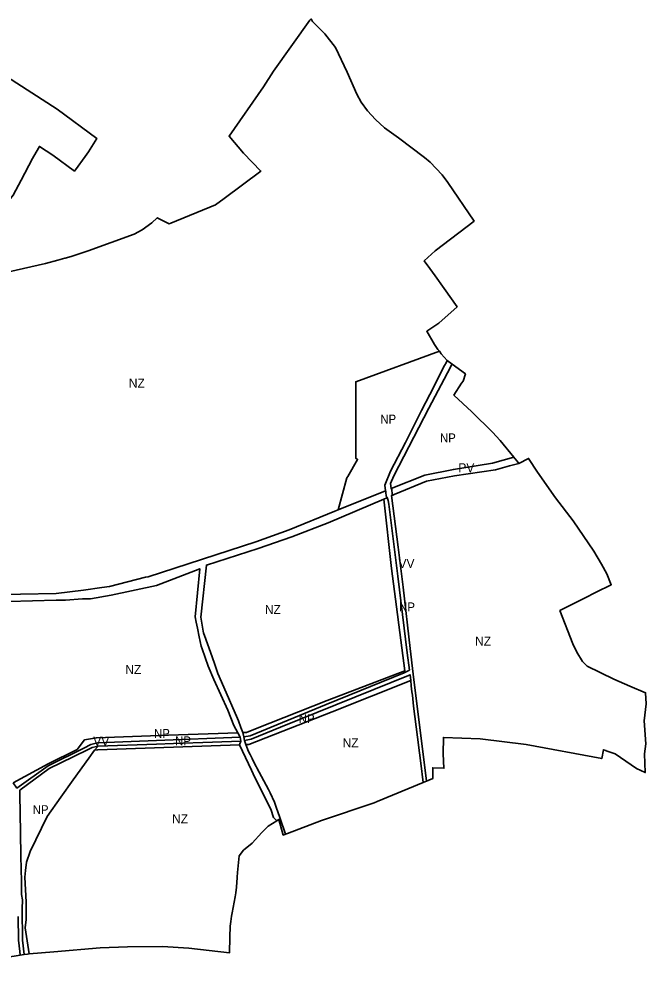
# Model space of a CAD drawing. Extents: x -650451 to -642268, y -1075216 to -1066610.
# Drawn here: x -643317 to -642268, y -1070593 to -1069004 of the extents above; entities that cross this region are included whole.
import ezdxf

# ---------------------------------------------------------------- set-up
doc = ezdxf.new("R2010")
doc.units = 0
doc.header["$LTSCALE"] = 6
doc.layers.add('1', color=7, linetype='Continuous', lineweight=35)
doc.layers.add('2', color=7, linetype='Continuous')
doc.layers.add('3', color=7, linetype='Continuous')

msp = doc.modelspace()

# ---------------------------------------------------------------- linework, layer by layer
at = {"layer": '1'}
for p, q in [((-642600.39, -1069574.87), (-642592.12, -1069580.95)), ((-642782.69, -1069824.93), (-642703.57, -1069792.88)), ((-642701.17, -1069804.49), (-642706.3, -1069806.69)), ((-642950.42, -1070197.58), (-642946.24, -1070204.83)), ((-642942.12, -1070197.4), (-642940.12, -1070204.42)), ((-642947.42, -1070217.64), (-642945.59, -1070211.49)), ((-642946.24, -1070204.83), (-642945.59, -1070211.49)), ((-642939.51, -1070210.35), (-642940.12, -1070204.42)), ((-642939.51, -1070210.35), (-642936.88, -1070217.27)), ((-643184.22, -1070220.08), (-643190.42, -1070226.99)), ((-642634.72, -1070278.46), (-642640.39, -1070280.82)), ((-643314.51, -1070569.69), (-643307.99, -1070568.66))]:
    msp.add_line(p, q, dxfattribs=at)
for points in [[(-642613.34, -1069559.68), (-642615.67, -1069556.39), (-642621.38, -1069548.32), (-642634.53, -1069526.26), (-642614.21, -1069512.57), (-642583.52, -1069485.34), (-642605.44, -1069454.72), (-642620.56, -1069433.59), (-642629.27, -1069421.41), (-642638.46, -1069408.57), (-642620.16, -1069391.43), (-642555.29, -1069342.03), (-642599.01, -1069277.25), (-642608.74, -1069264.5), (-642628.74, -1069243.14), (-642638.04, -1069235.61), (-642681.9, -1069202.83), (-642705.02, -1069185.92), (-642720.3, -1069172.09), (-642733.38, -1069157.41), (-642744.33, -1069142.96), (-642751.46, -1069129.7), (-642767.68, -1069092.94), (-642787.11, -1069051.51), (-642804.62, -1069028.48), (-642825.24, -1069008.13), (-642827.83, -1069003.93), (-642829.78, -1069005.85), (-642890.6, -1069090.98), (-642907.25, -1069117.59), (-642964.96, -1069199.73), (-642940.94, -1069228.19), (-642911.84, -1069258.15), (-642973.15, -1069303.98), (-642987.79, -1069314.92), (-643062.55, -1069345.13), (-643065.5, -1069346.32), (-643079.76, -1069339.05), (-643085.3, -1069336.22), (-643094.39, -1069344.93), (-643110.6, -1069356.48), (-643123.85, -1069363.76), (-643200.76, -1069391.51), (-643229.39, -1069400.85), (-643239.08, -1069403.7), (-643239.98, -1069403.97), (-643251.76, -1069407.44), (-643272.03, -1069412.65), (-643333.4, -1069426.8)], [(-643345.65, -1069418.15), (-643392.16, -1069386.88), (-643356.97, -1069342), (-643349.53, -1069332.52), (-643334.48, -1069309.27), (-643326.25, -1069298.47), (-643312.8, -1069273.59), (-643294.09, -1069237.23), (-643291.96, -1069233.54), (-643282.39, -1069216.93), (-643259.72, -1069231.55), (-643223.83, -1069258.21), (-643222.16, -1069255.97), (-643205.79, -1069233.92), (-643199.98, -1069226.2), (-643186.13, -1069203.94), (-643252.85, -1069154.56), (-643337.18, -1069100.04), (-643350.47, -1069098.91), (-643355.79, -1069099.42), (-643386.77, -1069143.32)], [(-642613.34, -1069559.68), (-642753.18, -1069610.65), (-642753.25, -1069738.59), (-642750.08, -1069740.57), (-642766.27, -1069769), (-642767.89, -1069771.42), (-642782.69, -1069824.93)], [(-642600.39, -1069574.87), (-642610.43, -1069563.79), (-642613.34, -1069559.68)], [(-642703.57, -1069792.88), (-642704.33, -1069783.54), (-642694.96, -1069760.17), (-642670.2, -1069712.37), (-642643.19, -1069658.58), (-642629.16, -1069631.94), (-642604.54, -1069583.67), (-642602.09, -1069578.86), (-642600.39, -1069574.87)], [(-642592.12, -1069580.95), (-642593.91, -1069584.46), (-642594.761, -1069586.091), (-642630.64, -1069654.82), (-642689.63, -1069767.81), (-642694.92, -1069780.68), (-642693.99, -1069788.85)], [(-642592.12, -1069580.95), (-642569.7, -1069597.42), (-642573.53, -1069609.34), (-642576.02, -1069613.14), (-642588.93, -1069632.86), (-642559.13, -1069661.18), (-642524.24, -1069694.66), (-642511.74, -1069708.63), (-642488.97, -1069736.54), (-642488.71, -1069736.85)], [(-642488.71, -1069736.85), (-642524.14, -1069746.8), (-642589.86, -1069757.1), (-642637.44, -1069766.81), (-642693.99, -1069788.85)], [(-642480.33, -1069747.1), (-642464, -1069738.83), (-642448.9, -1069761.88), (-642419.08, -1069804.61), (-642389.46, -1069843.4), (-642354.94, -1069894.06), (-642342.3, -1069915.7), (-642332.99, -1069931.63), (-642325.76, -1069950.18), (-642350.88, -1069962.69), (-642370.76, -1069972.6), (-642411.52, -1069993.17), (-642390.2, -1070048.75), (-642383.53, -1070062.65), (-642374.12, -1070078.53), (-642366.26, -1070086.08), (-642321.52, -1070108.08), (-642294.55, -1070119.7), (-642268.3, -1070130.58), (-642267.61, -1070149.35), (-642270.93, -1070177.77), (-642267.95, -1070216.15), (-642270.15, -1070232.65), (-642268.98, -1070264.17), (-642283.43, -1070257.44), (-642319.35, -1070232.74), (-642334.07, -1070227.7), (-642335.01, -1070227.38), (-642338.84, -1070226.07), (-642341.74, -1070240.74), (-642468.21, -1070217.46), (-642544.88, -1070207.97), (-642606.43, -1070205.41), (-642607.11, -1070232.78), (-642605.67, -1070256.87), (-642624.37, -1070256.25), (-642624.34, -1070274.14), (-642630.76, -1070276.81), (-642630.85, -1070276.85), (-642634.72, -1070278.46)], [(-642480.33, -1069747.1), (-642483.3, -1069743.48), (-642486.84, -1069739.15), (-642487.57, -1069738.25), (-642488.71, -1069736.85)], [(-642480.33, -1069747.1), (-642495.77, -1069751.44), (-642519.23, -1069757.95), (-642587.7, -1069767.66), (-642634.56, -1069777.05), (-642688.78, -1069798.98), (-642691.36, -1069800.03)], [(-642940.12, -1070204.42), (-642930.02, -1070202.54), (-642802.38, -1070150.51), (-642671.9, -1070097.32), (-642663.28, -1070092.67), (-642667.19, -1070063.71), (-642682.78, -1069935.98), (-642697.64, -1069815.14), (-642698.77, -1069809.17), (-642700.34, -1069804.12), (-642701.17, -1069804.49)], [(-642703.57, -1069792.88), (-642702.88, -1069794.95), (-642702.69, -1069795.44), (-642702.12, -1069801.89), (-642701.95, -1069802.35), (-642701.17, -1069804.49)], [(-642691.36, -1069800.03), (-642691.98, -1069798.57), (-642692.18, -1069798.08), (-642692.81, -1069791.58), (-642693, -1069791.05), (-642693.99, -1069788.85)], [(-642691.36, -1069800.03), (-642693.36, -1069800.94), (-642682.32, -1069887.43), (-642674.06, -1069953.91), (-642662.41, -1070056.78), (-642657.01, -1070099.49), (-642653.52, -1070126.99), (-642640.31, -1070233.47), (-642634.72, -1070278.46)], [(-642942.12, -1070197.4), (-642945.15, -1070188.91), (-642949.08, -1070177.91), (-642950.79, -1070174.04), (-642974.01, -1070121.34), (-642983.92, -1070098.38), (-642989.73, -1070081.96), (-642996.28, -1070063.04), (-643003.33, -1070042.66), (-643003.95, -1070040.85), (-643007.79, -1070030.29), (-643008.67, -1070027.69), (-643012.58, -1070004.56), (-643002.88, -1069917.33), (-642916.68, -1069889.38), (-642860.07, -1069870.09), (-642799.26, -1069846.42), (-642706.3, -1069806.69)], [(-642942.12, -1070197.4), (-642936.02, -1070197.23), (-642921.03, -1070191.32), (-642801.19, -1070143.75), (-642671.23, -1070094.16), (-642693.2, -1069922.89), (-642706.3, -1069806.69)], [(-643419.62, -1069963.66), (-643419.27, -1069968.58), (-643373.94, -1069966.68), (-643254.27, -1069964.45), (-643208.32, -1069959.24), (-643177.66, -1069954.76), (-643165.1, -1069952.97), (-643104.67, -1069937.61), (-643100.67, -1069936.63), (-642920.18, -1069878.46), (-642864.62, -1069858.27), (-642788.08, -1069827.14), (-642782.69, -1069824.93)], [(-642950.42, -1070197.58), (-642957.12, -1070185.74), (-642967.1, -1070159.77), (-642990.44, -1070108.4), (-643000.04, -1070086.48), (-643010.27, -1070057.2), (-643011.64, -1070052.91), (-643015.19, -1070037.32), (-643017.99, -1070022.61), (-643019.9, -1070012.55), (-643021.83, -1070003.51), (-643014.02, -1069923.38), (-643086.47, -1069951.48), (-643162.5, -1069967.46), (-643196.69, -1069973.45), (-643205.72, -1069973.77), (-643210.04, -1069973.92), (-643238.86, -1069975.91), (-643254.4, -1069976.15), (-643373.64, -1069979.08)], [(-642661.13, -1070110.48), (-642662.32, -1070100.64), (-642879.2, -1070188.43), (-642928.07, -1070208.21), (-642939.51, -1070210.35)], [(-642661.13, -1070110.48), (-642792.87, -1070162.36), (-642931.88, -1070217.1), (-642936.88, -1070217.27)], [(-642640.39, -1070280.82), (-642644.06, -1070248.54), (-642646.76, -1070231.29), (-642649.61, -1070205.1), (-642656.54, -1070153.14), (-642658.44, -1070135.02), (-642659.28, -1070129.09), (-642660.65, -1070119.2), (-642661.13, -1070110.48)], [(-643326.26, -1070281.43), (-643267.55, -1070249.49), (-643219.4, -1070225.8), (-643207.1, -1070209.72), (-643187.06, -1070205.98), (-643066.26, -1070201.69), (-642950.42, -1070197.58)], [(-643326.26, -1070281.43), (-643320, -1070290.2), (-643267.75, -1070252.77), (-643208.09, -1070223.14), (-643196.16, -1070217.22), (-643185.16, -1070214.62), (-643086.36, -1070210.57), (-642946.24, -1070204.83)], [(-642945.59, -1070211.49), (-642992.64, -1070213.18), (-643058.07, -1070215.38), (-643086.58, -1070216.57), (-643184.22, -1070220.08)], [(-642936.88, -1070217.27), (-642932.4, -1070228.91), (-642929.96, -1070233.8), (-642926.46, -1070240.85), (-642922.84, -1070248.13), (-642919.99, -1070253.87), (-642918.56, -1070256.37), (-642899.12, -1070292.53), (-642896.56, -1070297.95), (-642889.22, -1070313.53), (-642886.52, -1070321.86), (-642880.4, -1070339.24), (-642870.91, -1070367.41)], [(-643184.22, -1070220.08), (-643194.11, -1070222.44), (-643199.63, -1070225.11), (-643225.87, -1070237.84), (-643265.93, -1070257.27), (-643315.11, -1070293.76), (-643315.02, -1070300.7), (-643314.14, -1070364.39), (-643313.65, -1070403.8), (-643312.07, -1070446.44), (-643312.07, -1070468.03), (-643310.68, -1070477.03), (-643311.45, -1070491.88), (-643310.74, -1070544.5), (-643307.99, -1070568.66)], [(-643190.42, -1070226.99), (-643199.67, -1070240.13), (-643225.66, -1070276.41), (-643246.36, -1070305.06), (-643269.16, -1070337.59), (-643297.63, -1070396.36), (-643303.88, -1070414.2), (-643305.45, -1070427.92), (-643306.64, -1070438.91), (-643304.73, -1070480.95), (-643304.63, -1070486.64), (-643304.23, -1070505.07), (-643304.71, -1070510.01), (-643306.03, -1070524.13), (-643299.3, -1070567.28)], [(-643190.42, -1070226.99), (-643184.86, -1070225.91), (-642947.42, -1070217.64)], [(-642885.18, -1070344.93), (-642890.89, -1070339.33), (-642895.36, -1070325.55), (-642911.8, -1070292.5), (-642924.77, -1070266.45), (-642927.75, -1070260.43), (-642947.42, -1070217.64)], [(-642870.91, -1070367.41), (-642870.85, -1070367.39), (-642867.41, -1070366.09), (-642810.19, -1070344.54), (-642722.16, -1070314.83), (-642717.24, -1070312.78), (-642640.39, -1070280.82)], [(-642870.91, -1070367.41), (-642874.36, -1070368.61), (-642881.6, -1070342.53), (-642884.49, -1070344.51), (-642885.18, -1070344.93)], [(-643299.3, -1070567.28), (-643257.97, -1070564.12), (-643180.96, -1070557.46), (-643135.27, -1070555.61), (-643076.38, -1070555.3), (-643032.18, -1070558.01), (-642964.43, -1070565.78), (-642963.7, -1070539.33), (-642963.01, -1070521.1), (-642962.24, -1070513.05), (-642961, -1070504.3), (-642959.92, -1070498.77), (-642954.66, -1070471.87), (-642953.86, -1070465.3), (-642952.73, -1070455.96), (-642951.72, -1070439.84), (-642951.66, -1070439.25), (-642950.81, -1070431.06), (-642948.2, -1070403.68), (-642941.08, -1070394.2), (-642926.56, -1070382.38), (-642910.45, -1070364.64), (-642899.82, -1070353.78), (-642885.18, -1070344.93)], [(-643317.9, -1070504.73), (-643317.08, -1070544.75), (-643315.27, -1070563.2), (-643314.51, -1070569.69)], [(-643314.51, -1070569.69), (-643380.08, -1070580.09), (-643380.35, -1070580.14), (-643385.72, -1070580.86), (-643452.22, -1070592.35), (-643454.28, -1070592.709)], [(-643299.3, -1070567.28), (-643302.55, -1070567.8), (-643307.99, -1070568.66)]]:
    msp.add_lwpolyline(points, dxfattribs=at)

# ---------------------------------------------------------------- texts
at = {"layer": '2'}
for s, p in [('NZ', (-643132.783, -1069620.491)), ('PV', (-642581.584, -1069761.901)), ('VV', (-642681.641, -1069921.995)), ('NZ', (-642905.206, -1069998.8)), ('NZ', (-642553.497, -1070051.999)), ('NZ', (-643138.693, -1070099.288)), ('VV', (-643192.266, -1070219.366)), ('NZ', (-642775.162, -1070221.943)), ('NZ', (-643060.371, -1070349.031))]:
    msp.add_text(s, height=15, dxfattribs=at).set_placement(p)
at = {"layer": '2', "width": 0.95}
msp.add_text('NP', height=15, dxfattribs=at).set_placement((-643293.545, -1070333.716))
at = {"layer": '3', "width": 0.95}
for p in [(-642712.032, -1069680.608), (-642612.227, -1069712.028), (-642680.52, -1069994.715), (-642848.526, -1070181.571), (-643090.644, -1070206.337), (-643055.343, -1070218.72)]:
    msp.add_text('NP', height=15, dxfattribs=at).set_placement(p)

doc.saveas('drawing.dxf')
